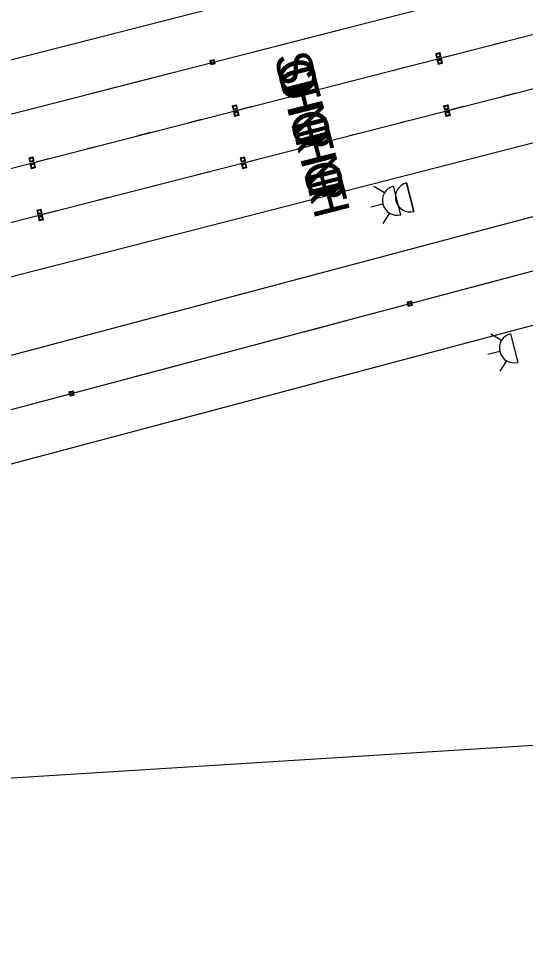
# Model space of a CAD drawing. Extents: x 2471014 to 2497726, y 6959577 to 6980268.
# Drawn here: x 2484936.2 to 2485052, y 6967746.2 to 6967959.8 of the extents above; entities that cross this region are included whole.
import ezdxf

# ---------------------------------------------------------------- set-up
doc = ezdxf.new("R2010")
doc.units = 0
for name, color, linetype in [('1', 7, 'Continuous'), ('13', 7, 'Continuous'), ('18', 7, 'Continuous'), ('23', 7, 'Continuous'), ('5', 7, 'Continuous'), ('59', 7, 'Continuous'), ('C-ANNO-NOTE', 7, 'Continuous'), ('C-COMM-IDEN', 7, 'Continuous'), ('Level 30', 7, 'Continuous'), ('Level 40', 7, 'Continuous'), ('p_structure fence', 7, 'Continuous'), ('RDWY_PAVE_XSTREET_FOC', 7, 'Continuous'), ('V7_25', 7, 'Continuous'), ('V7_50', 7, 'Continuous')]:
    doc.layers.add(name, color=color, linetype=linetype)

msp = doc.modelspace()

# ---------------------------------------------------------------- linework, layer by layer
at = {"layer": '1'}
for p, q in [((2485040.14, 6967898.52), (2485049.8, 6967901.09)), ((2485001.48, 6967888.25), (2485011.14, 6967890.82)), ((2484962.82, 6967877.99), (2484972.48, 6967880.55))]:
    msp.add_line(p, q, dxfattribs=at)
at = {"layer": '13'}
msp.add_line((2484868.6, 6967865.38), (2485090.9, 6967924.42), dxfattribs=at)
at = {"layer": '18'}
for p, q in [((2484287.61, 6967735.06), (2485876.76, 6968142.35)), ((2484874.76, 6967842.18), (2485097.06, 6967901.22))]:
    msp.add_line(p, q, dxfattribs=at)
at = {"layer": '23'}
for p, q in [((2485031.54, 6967951.79), (2485032.52, 6967952.04)), ((2485031.74, 6967951.67), (2485031.54, 6967951.79)), ((2485031.54, 6967951.79), (2485031.61, 6967951.53)), ((2485031.91, 6967951.02), (2485031.74, 6967951.67)), ((2485032.52, 6967952.04), (2485032.4, 6967951.84)), ((2485032.4, 6967951.84), (2485032.43, 6967951.7)), ((2485032.43, 6967951.7), (2485032.57, 6967951.19)), ((2485032.78, 6967951.06), (2485032.52, 6967952.04)), ((2484979.91, 6967950.19), (2484980.89, 6967950.44)), ((2484980.12, 6967950.06), (2484979.91, 6967950.19)), ((2484979.91, 6967950.19), (2484980.16, 6967949.21)), ((2484980.25, 6967949.54), (2484980.12, 6967950.06)), ((2484981.15, 6967949.46), (2484980.16, 6967949.21)), ((2484980.29, 6967949.4), (2484980.25, 6967949.54)), ((2484980.89, 6967950.44), (2484980.78, 6967950.23)), ((2484980.78, 6967950.23), (2484980.94, 6967949.57)), ((2484981.08, 6967949.72), (2484980.89, 6967950.44)), ((2484980.94, 6967949.57), (2484981.15, 6967949.46)), ((2484981.15, 6967949.46), (2484981.08, 6967949.72)), ((2485031.61, 6967951.53), (2485031.79, 6967950.8)), ((2485032.78, 6967951.06), (2485031.79, 6967950.8)), ((2485031.79, 6967950.8), (2485031.91, 6967951.02)), ((2485031.87, 6967950.32), (2485032.86, 6967950.58)), ((2485032.08, 6967950.21), (2485031.87, 6967950.32)), ((2485031.87, 6967950.32), (2485031.94, 6967950.06)), ((2485031.94, 6967950.06), (2485032.12, 6967949.34)), ((2485032.24, 6967949.55), (2485032.08, 6967950.21)), ((2485033.11, 6967949.59), (2485032.12, 6967949.34)), ((2485032.12, 6967949.34), (2485032.24, 6967949.55)), ((2485032.57, 6967951.19), (2485032.78, 6967951.06)), ((2485032.86, 6967950.58), (2485032.73, 6967950.38)), ((2485032.73, 6967950.38), (2485032.77, 6967950.24)), ((2485032.77, 6967950.24), (2485032.9, 6967949.72)), ((2485033.11, 6967949.59), (2485032.86, 6967950.58)), ((2485032.9, 6967949.72), (2485033.11, 6967949.59)), ((2484980.16, 6967949.21), (2484980.29, 6967949.4)), ((2484985.04, 6967939.87), (2484986.03, 6967940.12)), ((2484985.25, 6967939.76), (2484985.04, 6967939.87)), ((2484985.04, 6967939.87), (2484985.11, 6967939.61)), ((2484985.11, 6967939.61), (2484985.3, 6967938.89)), ((2484985.41, 6967939.1), (2484985.25, 6967939.76)), ((2484986.28, 6967939.14), (2484985.3, 6967938.89)), ((2484985.3, 6967938.89), (2484985.41, 6967939.1)), ((2484986.03, 6967940.12), (2484985.9, 6967939.93)), ((2484985.9, 6967939.93), (2484985.94, 6967939.79)), ((2484985.94, 6967939.79), (2484986.07, 6967939.27)), ((2484986.28, 6967939.14), (2484986.03, 6967940.12)), ((2484986.07, 6967939.27), (2484986.28, 6967939.14)), ((2485033.36, 6967939.86), (2485034.34, 6967940.11)), ((2485033.56, 6967939.75), (2485033.36, 6967939.86)), ((2485033.36, 6967939.86), (2485033.42, 6967939.6)), ((2485033.42, 6967939.6), (2485033.61, 6967938.88)), ((2485033.72, 6967939.1), (2485033.56, 6967939.75)), ((2485034.59, 6967939.13), (2485033.61, 6967938.88)), ((2485033.61, 6967938.88), (2485033.72, 6967939.1)), ((2485034.34, 6967940.11), (2485034.21, 6967939.92)), ((2485034.21, 6967939.92), (2485034.25, 6967939.78)), ((2485034.25, 6967939.78), (2485034.38, 6967939.26)), ((2485034.59, 6967939.13), (2485034.34, 6967940.11)), ((2485034.38, 6967939.26), (2485034.59, 6967939.13)), ((2484985.38, 6967938.41), (2484986.36, 6967938.66)), ((2484985.58, 6967938.29), (2484985.38, 6967938.41)), ((2484985.38, 6967938.41), (2484985.44, 6967938.15)), ((2484985.44, 6967938.15), (2484985.63, 6967937.42)), ((2484985.75, 6967937.64), (2484985.58, 6967938.29)), ((2484986.61, 6967937.68), (2484985.63, 6967937.42)), ((2484985.63, 6967937.42), (2484985.75, 6967937.64)), ((2484986.36, 6967938.66), (2484986.23, 6967938.46)), ((2484986.23, 6967938.46), (2484986.27, 6967938.32)), ((2484986.27, 6967938.32), (2484986.4, 6967937.81)), ((2484986.61, 6967937.68), (2484986.36, 6967938.66)), ((2484986.4, 6967937.81), (2484986.61, 6967937.68)), ((2485033.67, 6967938.4), (2485034.66, 6967938.65)), ((2485033.88, 6967938.28), (2485033.67, 6967938.4)), ((2485033.67, 6967938.4), (2485033.74, 6967938.14)), ((2485033.74, 6967938.14), (2485033.93, 6967937.42)), ((2485034.04, 6967937.63), (2485033.88, 6967938.28)), ((2485034.91, 6967937.67), (2485033.93, 6967937.42)), ((2485033.93, 6967937.42), (2485034.04, 6967937.63)), ((2485034.66, 6967938.65), (2485034.53, 6967938.45)), ((2485034.53, 6967938.45), (2485034.57, 6967938.31)), ((2485034.57, 6967938.31), (2485034.7, 6967937.8)), ((2485034.91, 6967937.67), (2485034.66, 6967938.65)), ((2485034.7, 6967937.8), (2485034.91, 6967937.67)), ((2484938.55, 6967927.95), (2484939.53, 6967928.21)), ((2484939.53, 6967928.21), (2484939.4, 6967928.01)), ((2484939.78, 6967927.22), (2484939.53, 6967928.21)), ((2484986.86, 6967927.95), (2484987.84, 6967928.2)), ((2484987.84, 6967928.2), (2484987.71, 6967928)), ((2484988.09, 6967927.22), (2484987.84, 6967928.2)), ((2484938.75, 6967927.84), (2484938.55, 6967927.95)), ((2484938.55, 6967927.95), (2484938.61, 6967927.69)), ((2484938.61, 6967927.69), (2484938.8, 6967926.97)), ((2484938.92, 6967927.18), (2484938.75, 6967927.84)), ((2484939.78, 6967927.22), (2484938.8, 6967926.97)), ((2484938.8, 6967926.97), (2484938.92, 6967927.18)), ((2484938.88, 6967926.49), (2484939.86, 6967926.74)), ((2484939.08, 6967926.38), (2484938.88, 6967926.49)), ((2484938.88, 6967926.49), (2484938.95, 6967926.23)), ((2484938.95, 6967926.23), (2484939.13, 6967925.51)), ((2484939.25, 6967925.72), (2484939.08, 6967926.38)), ((2484939.4, 6967928.01), (2484939.44, 6967927.87)), ((2484939.44, 6967927.87), (2484939.57, 6967927.35)), ((2484939.57, 6967927.35), (2484939.78, 6967927.22)), ((2484939.86, 6967926.74), (2484939.74, 6967926.54)), ((2484939.74, 6967926.54), (2484939.77, 6967926.41)), ((2484939.77, 6967926.41), (2484939.91, 6967925.89)), ((2484940.11, 6967925.76), (2484939.86, 6967926.74)), ((2484987.06, 6967927.83), (2484986.86, 6967927.95)), ((2484986.86, 6967927.95), (2484986.92, 6967927.69)), ((2484986.92, 6967927.69), (2484987.11, 6967926.97)), ((2484987.23, 6967927.18), (2484987.06, 6967927.83)), ((2484988.09, 6967927.22), (2484987.11, 6967926.97)), ((2484987.11, 6967926.97), (2484987.23, 6967927.18)), ((2484987.18, 6967926.48), (2484988.16, 6967926.73)), ((2484987.38, 6967926.37), (2484987.18, 6967926.48)), ((2484987.18, 6967926.48), (2484987.24, 6967926.22)), ((2484987.24, 6967926.22), (2484987.43, 6967925.5)), ((2484987.55, 6967925.71), (2484987.38, 6967926.37)), ((2484987.71, 6967928), (2484987.75, 6967927.86)), ((2484987.75, 6967927.86), (2484987.88, 6967927.35)), ((2484987.88, 6967927.35), (2484988.09, 6967927.22)), ((2484988.16, 6967926.73), (2484988.03, 6967926.53)), ((2484988.03, 6967926.53), (2484988.07, 6967926.4)), ((2484988.07, 6967926.4), (2484988.2, 6967925.88)), ((2484988.41, 6967925.75), (2484988.16, 6967926.73)), ((2484940.11, 6967925.76), (2484939.13, 6967925.51)), ((2484939.13, 6967925.51), (2484939.25, 6967925.72)), ((2484939.91, 6967925.89), (2484940.11, 6967925.76)), ((2484988.41, 6967925.75), (2484987.43, 6967925.5)), ((2484987.43, 6967925.5), (2484987.55, 6967925.71)), ((2484988.2, 6967925.88), (2484988.41, 6967925.75)), ((2484940.36, 6967916.03), (2484941.34, 6967916.28)), ((2484940.56, 6967915.92), (2484940.36, 6967916.03)), ((2484940.36, 6967916.03), (2484940.43, 6967915.77)), ((2484940.43, 6967915.77), (2484940.61, 6967915.05)), ((2484940.73, 6967915.26), (2484940.56, 6967915.92)), ((2484941.59, 6967915.3), (2484940.61, 6967915.05)), ((2484941.34, 6967916.28), (2484941.22, 6967916.08)), ((2484941.22, 6967916.08), (2484941.25, 6967915.95)), ((2484941.25, 6967915.95), (2484941.39, 6967915.43)), ((2484941.59, 6967915.3), (2484941.34, 6967916.28)), ((2484941.39, 6967915.43), (2484941.59, 6967915.3)), ((2484940.61, 6967915.05), (2484940.73, 6967915.26)), ((2484940.68, 6967914.56), (2484941.66, 6967914.81)), ((2484940.88, 6967914.45), (2484940.68, 6967914.56)), ((2484940.68, 6967914.56), (2484940.75, 6967914.3)), ((2484940.75, 6967914.3), (2484940.93, 6967913.58)), ((2484941.05, 6967913.79), (2484940.88, 6967914.45)), ((2484941.91, 6967913.83), (2484940.93, 6967913.58)), ((2484940.93, 6967913.58), (2484941.05, 6967913.79)), ((2484941.66, 6967914.81), (2484941.54, 6967914.62)), ((2484941.54, 6967914.62), (2484941.57, 6967914.48)), ((2484941.57, 6967914.48), (2484941.71, 6967913.96)), ((2484941.91, 6967913.83), (2484941.66, 6967914.81)), ((2484941.71, 6967913.96), (2484941.91, 6967913.83)), ((2485025.02, 6967895.02), (2485026.01, 6967895.28)), ((2485025.23, 6967894.91), (2485025.02, 6967895.02)), ((2485025.02, 6967895.02), (2485025.09, 6967894.76)), ((2485025.09, 6967894.76), (2485025.28, 6967894.04)), ((2485025.4, 6967894.26), (2485025.23, 6967894.91)), ((2485026.26, 6967894.3), (2485025.28, 6967894.04)), ((2485025.28, 6967894.04), (2485025.4, 6967894.26)), ((2485026.01, 6967895.28), (2485025.88, 6967895.08)), ((2485025.88, 6967895.08), (2485025.92, 6967894.95)), ((2485025.92, 6967894.95), (2485026.06, 6967894.43)), ((2485026.26, 6967894.3), (2485026.01, 6967895.28)), ((2485026.06, 6967894.43), (2485026.26, 6967894.3)), ((2484947.7, 6967874.49), (2484948.69, 6967874.75)), ((2484948.69, 6967874.75), (2484948.56, 6967874.55)), ((2484948.95, 6967873.77), (2484948.69, 6967874.75)), ((2484947.91, 6967874.38), (2484947.7, 6967874.49)), ((2484947.7, 6967874.49), (2484947.77, 6967874.23)), ((2484947.77, 6967874.23), (2484947.97, 6967873.51)), ((2484948.08, 6967873.72), (2484947.91, 6967874.38)), ((2484948.95, 6967873.77), (2484947.97, 6967873.51)), ((2484947.97, 6967873.51), (2484948.08, 6967873.72)), ((2484948.56, 6967874.55), (2484948.6, 6967874.41)), ((2484948.6, 6967874.41), (2484948.74, 6967873.9)), ((2484948.74, 6967873.9), (2484948.95, 6967873.77))]:
    msp.add_line(p, q, dxfattribs=at)
for points in [[(2485031.74, 6967951.67), (2485032.4, 6967951.84), (2485032.57, 6967951.19), (2485031.91, 6967951.02)], [(2484980.94, 6967949.57), (2484980.29, 6967949.4), (2484980.12, 6967950.06), (2484980.78, 6967950.23)], [(2485032.08, 6967950.21), (2485032.73, 6967950.38), (2485032.9, 6967949.72), (2485032.24, 6967949.55)], [(2484985.25, 6967939.76), (2484985.9, 6967939.93), (2484986.07, 6967939.27), (2484985.41, 6967939.1)], [(2485033.56, 6967939.75), (2485034.21, 6967939.92), (2485034.38, 6967939.26), (2485033.72, 6967939.1)], [(2484985.58, 6967938.29), (2484986.23, 6967938.46), (2484986.4, 6967937.81), (2484985.75, 6967937.64)], [(2485033.88, 6967938.28), (2485034.53, 6967938.45), (2485034.7, 6967937.8), (2485034.04, 6967937.63)], [(2484938.75, 6967927.84), (2484939.4, 6967928.01), (2484939.57, 6967927.35), (2484938.92, 6967927.18)], [(2484939.08, 6967926.38), (2484939.74, 6967926.54), (2484939.91, 6967925.89), (2484939.25, 6967925.72)], [(2484987.06, 6967927.83), (2484987.71, 6967928), (2484987.88, 6967927.35), (2484987.23, 6967927.18)], [(2484987.38, 6967926.37), (2484988.03, 6967926.53), (2484988.2, 6967925.88), (2484987.55, 6967925.71)], [(2484940.56, 6967915.92), (2484941.22, 6967916.08), (2484941.39, 6967915.43), (2484940.73, 6967915.26)], [(2484940.88, 6967914.45), (2484941.54, 6967914.62), (2484941.71, 6967913.96), (2484941.05, 6967913.79)], [(2485025.23, 6967894.91), (2485025.88, 6967895.08), (2485026.06, 6967894.43), (2485025.4, 6967894.26)], [(2484947.91, 6967874.38), (2484948.56, 6967874.55), (2484948.74, 6967873.9), (2484948.08, 6967873.72)]]:
    msp.add_lwpolyline(points, close=True, dxfattribs=at)
at = {"layer": '5'}
msp.add_arc((2479474.04, 6969335.88), 8460, 6.37617, 6.37617, dxfattribs=at)
at = {"layer": '59'}
for p, q in [((2484247.64, 6967749.59), (2485580.2, 6968091.11)), ((2484442.23, 6967787.08), (2485583.18, 6968079.49))]:
    msp.add_line(p, q, dxfattribs=at)
at = {"layer": 'C-ANNO-NOTE'}
msp.add_line((2484871.73, 6967853.8), (2485094.03, 6967912.83), dxfattribs=at)
at = {"layer": 'C-COMM-IDEN'}
for p, q in [((2485024.88, 6967922.26), (2485026.51, 6967915.71)), ((2485026.51, 6967915.71), (2485024.88, 6967922.26)), ((2485019.84, 6967919.99), (2485017.41, 6967921.4)), ((2485023.55, 6967914.97), (2485021.91, 6967921.52)), ((2485019.46, 6967917.43), (2485016.73, 6967916.75)), ((2485020.99, 6967915.35), (2485019.46, 6967913))]:
    msp.add_line(p, q, dxfattribs=at)
for centre in [(2485025.7, 6967918.99), (2485022.73, 6967918.25)]:
    msp.add_arc(centre, 3.37, 104.0161, 284.0161, dxfattribs=at)
at = {"layer": 'Level 30'}
for p, q in [((2485046.59, 6967886.27), (2485044.16, 6967887.69)), ((2485048.67, 6967887.8), (2485050.29, 6967881.25)), ((2485046.2, 6967883.71), (2485043.47, 6967883.04)), ((2485047.74, 6967881.63), (2485046.19, 6967879.28))]:
    msp.add_line(p, q, dxfattribs=at)
msp.add_arc((2485049.48, 6967884.52), 3.37, 103.883, 283.883, dxfattribs=at)
at = {"layer": 'Level 40'}
for p, q in [((2485044.91, 6967953.93), (2485047.82, 6967954.67)), ((2485033.29, 6967950.95), (2485036.19, 6967951.69)), ((2485021.66, 6967947.97), (2485024.57, 6967948.71)), ((2485010.04, 6967944.99), (2485012.95, 6967945.73)), ((2484998.41, 6967942.01), (2485001.32, 6967942.75)), ((2485046.7, 6967941.99), (2485049.6, 6967942.74)), ((2484986.79, 6967939.03), (2484989.7, 6967939.77)), ((2485035.07, 6967939.02), (2485037.98, 6967939.76)), ((2484975.17, 6967936.05), (2484978.07, 6967936.8)), ((2485023.45, 6967936.04), (2485026.35, 6967936.78)), ((2484963.54, 6967933.07), (2484966.45, 6967933.82)), ((2485011.82, 6967933.06), (2485014.73, 6967933.8)), ((2484951.92, 6967930.09), (2484954.82, 6967930.84)), ((2485000.2, 6967930.08), (2485003.1, 6967930.82)), ((2484940.29, 6967927.11), (2484943.2, 6967927.86)), ((2484988.57, 6967927.1), (2484991.48, 6967927.84)), ((2484976.95, 6967924.12), (2484979.86, 6967924.86)), ((2484965.33, 6967921.14), (2484968.23, 6967921.89)), ((2484953.7, 6967918.16), (2484956.61, 6967918.91)), ((2484942.08, 6967915.18), (2484944.98, 6967915.93))]:
    msp.add_line(p, q, dxfattribs=at)
at = {"layer": 'RDWY_PAVE_XSTREET_FOC'}
for p, q in [((2484949.58, 6967954.27), (2484968.95, 6967959.23)), ((2484990.22, 6967952.3), (2485009.59, 6967957.26)), ((2484951.47, 6967942.37), (2484970.84, 6967947.33))]:
    msp.add_line(p, q, dxfattribs=at)
at = {"layer": 'V7_25'}
for p, q in [((2484241.91, 6967772.9), (2485864.85, 6968188.84)), ((2484244.68, 6967761.22), (2485577.22, 6968102.74))]:
    msp.add_line(p, q, dxfattribs=at)
at = {"layer": 'V7_50'}
msp.add_lwpolyline([(2484447.6, 6967710.17), (2484746.88, 6967763.8), (2484810.56, 6967778.56), (2485254.64, 6967806.33), (2486523.86, 6968131.62), (2487206.36, 6968296.54)], dxfattribs=at)

# ---------------------------------------------------------------- texts
at = {"layer": 'p_structure fence'}
for s, p in [('S', (2484994.55, 6967951.14)), ('O', (2484994.95, 6967949.56)), ('U', (2484995.38, 6967947.91)), ('T', (2484995.78, 6967946.35)), ('H', (2484996.18, 6967944.78)), ('N', (2484997.57, 6967939.36)), ('O', (2484997.97, 6967937.78)), ('R', (2484998.39, 6967936.13)), ('T', (2484998.8, 6967934.57)), ('H', (2484999.2, 6967933)), ('N', (2485000.55, 6967927.74)), ('O', (2485000.95, 6967926.16)), ('R', (2485001.37, 6967924.51)), ('T', (2485001.78, 6967922.95)), ('H', (2485002.18, 6967921.38))]:
    msp.add_text(s, height=8.2, rotation=284.3007, dxfattribs=at).set_placement(p)

doc.saveas('drawing.dxf')
